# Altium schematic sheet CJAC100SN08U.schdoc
size 127 x 101 mm
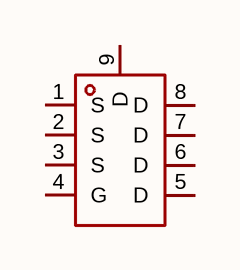
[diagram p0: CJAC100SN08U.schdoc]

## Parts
Q?  cjac100sn08u  [PDFN-8_L5.8-W4.9-P1.27-LS6.1-BL-A]  (value not drawn)

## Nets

Not connected (* = marked no-connect by the designer): Q? 1(S) 2(S) 3(S) 4(G) 5(D) 6(D) 7(D) 8(D) 9(D)

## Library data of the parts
Q? = cjac100sn08u: 数量:1个N沟道;漏源电压(Vdss):80V;连续漏极电流(Id):100A;导通电阻(RDS(on)):3.9mΩ@10V;耗散功率(Pd):104W;阈值电压(Vgs(th)):4V;; Manufacturer: CJ(江苏长电/长晶); AddInBom: yes; ModelId: 450a83d8ea544a1683b51becadb75d8a; ModelTransform: 200.787,238.189,0,0,0,0,-0.005,0.003,0; Number: 1个N沟道; Drain to Source Voltage: 80V; Current - Continuous Drain(Id): 100A; Pd - Power Dissipation: 104W; Gate Threshold Voltage (Vgs(th)): 4V; Gate Charge(Qg): 60nC@10V; Input Capacitance(Ciss): 3.78nF; Reverse Transfer Capacitance (Crss@Vds): 25pF; Type: N沟道; Output Capacitance(Coss): 1.8nF; Vgs: ±20V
